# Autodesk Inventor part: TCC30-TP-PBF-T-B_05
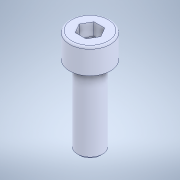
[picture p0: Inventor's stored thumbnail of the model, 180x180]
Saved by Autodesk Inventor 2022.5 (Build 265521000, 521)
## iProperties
Created: 2023-09
Part Number: TCC30-TP-PBF-T-B_05
Material: 一般
Document SubType Name: Modeling
Designer: ImaoCorp
Density: 1 g/cm^3
Appearance: 既定
Author: ImaoCorp
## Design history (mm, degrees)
feature "TCC30-TP-PBF-T-B_05"
node "ソリッド1"
